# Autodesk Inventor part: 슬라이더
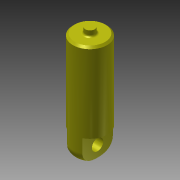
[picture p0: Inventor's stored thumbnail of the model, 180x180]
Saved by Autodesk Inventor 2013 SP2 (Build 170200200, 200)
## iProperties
Created: 2016-08
Part Number: 슬라이더
Material: 강철, 탄소
Document SubType Name: Modeling
Designer: mduedu
Density: 7.87 g/cm^3
Author: mduedu
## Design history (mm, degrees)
sketch "스케치1"
  geometry: C1 r 9 at (0, 0); 1 further point
  constraints: 1 centre point, 1 coincident
  dimensions: "d0" = 18 diameter of C1
extrude "돌출1" new body sketch "스케치1" distance "d1" = 55; taper "d2" = 0 deg
fillet "모깎기1" dims "d21" = 6
sketch "스케치6"
  geometry: L1 (9, 6)-(9, 55) reference; L2 (-9, 6)-(-9, 55) reference; L3 (9, 55)-(-9, 55) reference; L4 (0, 55)-(0, 0); L5 (9, 13)-(4, 13); L6 (4, 13)-(4, 0); L7 (4, 0)-(9, 0); L8 (9, 0)-(9, 13); L9 (-9, 13)-(-4, 13); L10 (-4, 13)-(-4, 0); L11 (-4, 0)-(-9, 0); L12 (-9, 0)-(-9, 13)
  constraints: 18 end point, 4 symmetric about line, 2 parallel, 2 perpendicular, 1 horizontal, 1 horizontal alignment, 1 midpoint, 1 point on line
  dimensions: "d22" = 13 distance of L7.end L5.start; "d24" = 4 distance between parallel lines of L6 L4
extrude "돌출5" cut sketch "스케치6" stored distance "d25" = 8; taper "d26" = 0 deg
sketch "스케치8"
  geometry: C1 r 3 at (6, 0); 1 further point
  constraints: 1 centre point, 1 horizontal alignment
  dimensions: "d27" = 6 diameter of C1; "d28" = 6 distance of point (0, 0) C1.centre
extrude "돌출6" cut sketch "스케치8" stored distance "d29" = 8; taper "d30" = 0 deg
chamfer "모따기2" distance "d43" = 1; stored, may be unused: second distance "d44" = 2, angle "d45" = 30 deg
sketch "스케치9"
  geometry: C1 r 2.5 at (0, 0); 1 further point
  constraints: 1 centre point, 1 coincident
  dimensions: "d47" = 5 diameter of C1
extrude "돌출7" join sketch "스케치9" distance "d48" = 3; taper "d49" = 0 deg
fillet "모깎기2" dims "d50" = 1
node "솔리드1"
